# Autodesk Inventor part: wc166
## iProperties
Shininess: 64.0
Length Units: 11272
Angle Units: 11279
Time Units: 11290
Mass Units: 11286
Length Display Precision: 3
Angle Display Precision: 2
Compacted: True
Part Number: wc166
Document SubType Name: Modeling
Created: 2004-08
Designer: John Blackburn
Manufacturer: Standard
Standards Organization: Custom
Material: Phenolic
Density: 0.0
Volumn: 0.0
Area: 0.0
PropertySet Name: Model Information
Control State: 0
Master: False
Checked Out: False
Author: John Blackburn
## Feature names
1. Base1
